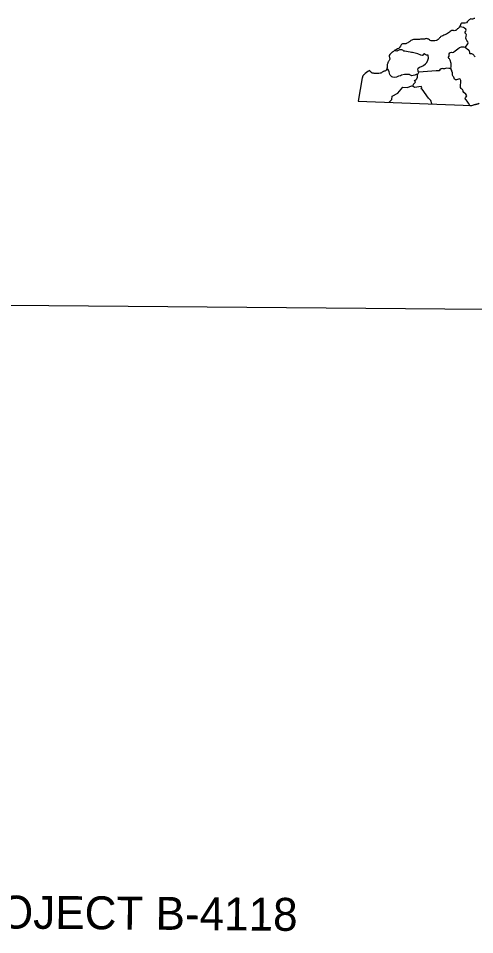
# Model space of a CAD drawing. Extents: x 1379453 to 1387082, y 594364 to 596664.
# Drawn here: x 1382008 to 1382285, y 595562 to 596118 of the extents above; entities that cross this region are included whole.
import ezdxf

# ---------------------------------------------------------------- set-up
doc = ezdxf.new("R2010")
doc.units = 0
for name, color, linetype in [('Old_Level_32', 7, 'Continuous'), ('Pattern 8', 7, 'Continuous'), ('Prop Horizontal Alignment Station Label', 7, 'Continuous')]:
    doc.layers.add(name, color=color, linetype=linetype)

msp = doc.modelspace()

# ---------------------------------------------------------------- linework, layer by layer
at = {"layer": 'Old_Level_32'}
msp.add_lwpolyline([(1380751.9, 595954.74), (1382700.35, 595938.42), (1382692.2, 594965.67), (1380743.75, 594981.99)], close=True, dxfattribs=at)
at = {"layer": 'Pattern 8'}
for points in [[(1382285.45, 596118.46), (1382285.01, 596118.31), (1382284.64, 596118.19), (1382284.2, 596118.04), (1382283.73, 596118.05), (1382283.14, 596118.12), (1382282.79, 596118.03), (1382282.54, 596117.81), (1382282.13, 596117.57), (1382281.69, 596117.1), (1382281.31, 596116.67), (1382280.96, 596116.27), (1382280.39, 596115.81), (1382279.73, 596115.6), (1382279.04, 596115.54), (1382278.2, 596115.58), (1382277.57, 596115.47), (1382277.13, 596115.22), (1382277, 596114.94), (1382276.81, 596114.66)], [(1382285.45, 596118.46), (1382285.01, 596118.31), (1382284.64, 596118.19), (1382284.2, 596118.04), (1382283.73, 596118.05), (1382283.14, 596118.12), (1382282.79, 596118.03), (1382282.54, 596117.81), (1382282.13, 596117.57), (1382281.69, 596117.1), (1382281.31, 596116.67), (1382280.96, 596116.27), (1382280.39, 596115.81), (1382279.73, 596115.6), (1382279.04, 596115.54), (1382278.2, 596115.58), (1382277.57, 596115.47), (1382277.13, 596115.22), (1382277, 596114.94), (1382276.81, 596114.66)], [(1382276.2, 596113.39), (1382276.11, 596113.11), (1382275.98, 596112.86), (1382275.66, 596112.55), (1382275.38, 596112.37), (1382274.91, 596112), (1382274.72, 596111.88), (1382274.56, 596111.69), (1382274.34, 596111.44), (1382274.15, 596111.26), (1382273.93, 596111.1), (1382273.64, 596110.98), (1382273.02, 596110.93), (1382272.68, 596111.06), (1382272.36, 596111.15), (1382272.02, 596111.16), (1382271.77, 596111.13), (1382271.46, 596111.01), (1382271.17, 596110.86), (1382270.51, 596110.4), (1382270.1, 596110.12), (1382269.6, 596109.66), (1382269.19, 596109.38), (1382268.93, 596109.2), (1382268.37, 596108.89), (1382267.8, 596108.62), (1382267.27, 596108.34), (1382266.73, 596108.19), (1382266.01, 596107.92), (1382265.42, 596107.71), (1382264.91, 596107.46), (1382264.72, 596107.19), (1382264.53, 596106.88), (1382264.15, 596106.6), (1382263.83, 596106.26), (1382263.2, 596105.58), (1382262.63, 596105.18), (1382262.16, 596105), (1382261.22, 596104.79), (1382260.44, 596104.74), (1382259.75, 596104.75), (1382259.1, 596104.85), (1382258.45, 596105.07), (1382257.95, 596105.36), (1382257.42, 596105.71), (1382257.11, 596105.9), (1382256.77, 596106.06), (1382256.24, 596106.13), (1382255.83, 596106.11), (1382255.39, 596105.96), (1382255.05, 596105.8), (1382254.45, 596105.75), (1382254.11, 596105.81), (1382253.64, 596105.85), (1382253.17, 596105.83), (1382253.02, 596105.83), (1382252.99, 596105.83)], [(1382276.2, 596113.39), (1382276.11, 596113.11), (1382275.98, 596112.86), (1382275.66, 596112.55), (1382275.38, 596112.37), (1382274.91, 596112), (1382274.72, 596111.88), (1382274.56, 596111.69), (1382274.34, 596111.44), (1382274.15, 596111.26), (1382273.93, 596111.1), (1382273.64, 596110.98), (1382273.02, 596110.93), (1382272.68, 596111.06), (1382272.36, 596111.15), (1382272.02, 596111.16), (1382271.77, 596111.13), (1382271.46, 596111.01), (1382271.17, 596110.86), (1382270.51, 596110.4), (1382270.1, 596110.12), (1382269.6, 596109.66), (1382269.19, 596109.38), (1382268.93, 596109.2), (1382268.37, 596108.89), (1382267.8, 596108.62), (1382267.27, 596108.34), (1382266.73, 596108.19), (1382266.01, 596107.92), (1382265.42, 596107.71), (1382264.91, 596107.46), (1382264.72, 596107.19), (1382264.53, 596106.88), (1382264.15, 596106.6), (1382263.83, 596106.26), (1382263.2, 596105.58), (1382262.63, 596105.18), (1382262.16, 596105), (1382261.22, 596104.79), (1382260.44, 596104.74), (1382259.75, 596104.75), (1382259.1, 596104.85), (1382258.45, 596105.07), (1382257.95, 596105.36), (1382257.42, 596105.71), (1382257.11, 596105.9), (1382256.77, 596106.06), (1382256.24, 596106.13), (1382255.83, 596106.11), (1382255.39, 596105.96), (1382255.05, 596105.8), (1382254.45, 596105.75), (1382254.11, 596105.81), (1382253.64, 596105.85), (1382253.17, 596105.83), (1382253.02, 596105.83), (1382252.99, 596105.83)], [(1382276.81, 596114.66), (1382276.78, 596114.41), (1382276.68, 596114.2), (1382276.56, 596114.04), (1382276.55, 596113.85), (1382276.43, 596113.64), (1382276.33, 596113.51), (1382276.2, 596113.39)], [(1382276.81, 596114.66), (1382276.78, 596114.41), (1382276.68, 596114.2), (1382276.56, 596114.04), (1382276.55, 596113.85), (1382276.43, 596113.64), (1382276.33, 596113.51), (1382276.2, 596113.39)], [(1382279.93, 596100.91), (1382281.23, 596102.95), (1382281.4, 596103.54), (1382281.19, 596104.2), (1382280.6, 596105.02), (1382280.2, 596105.75), (1382280.15, 596106.4), (1382280.32, 596107.59), (1382280.46, 596108.52), (1382280.37, 596108.78), (1382279.9, 596109.19), (1382279.56, 596109.57), (1382279.7, 596110.1), (1382280.02, 596110.69), (1382280.24, 596111.28), (1382280, 596111.94), (1382279.32, 596112.51), (1382278.6, 596112.89), (1382277.7, 596113), (1382276.73, 596113.23), (1382276.2, 596113.39)], [(1382279.93, 596100.91), (1382281.23, 596102.95), (1382281.4, 596103.54), (1382281.19, 596104.2), (1382280.6, 596105.02), (1382280.2, 596105.75), (1382280.15, 596106.4), (1382280.32, 596107.59), (1382280.46, 596108.52), (1382280.37, 596108.78), (1382279.9, 596109.19), (1382279.56, 596109.57), (1382279.7, 596110.1), (1382280.02, 596110.69), (1382280.24, 596111.28), (1382280, 596111.94), (1382279.32, 596112.51), (1382278.6, 596112.89), (1382277.7, 596113), (1382276.73, 596113.23), (1382276.2, 596113.39)], [(1382252.99, 596105.83), (1382252.64, 596105.74), (1382251.95, 596105.68), (1382251.33, 596105.63), (1382250.42, 596105.61), (1382249.8, 596105.68), (1382249.01, 596105.66), (1382248.26, 596105.57), (1382247.73, 596105.46), (1382247.23, 596105.27), (1382246.76, 596105), (1382246.41, 596104.72), (1382246.06, 596104.44), (1382245.75, 596104.14), (1382245.4, 596103.92), (1382245.08, 596103.71), (1382244.77, 596103.52), (1382244.27, 596103.31), (1382244.11, 596103.12), (1382243.67, 596103.07), (1382243.29, 596103.04), (1382242.92, 596103.05), (1382242.45, 596102.99), (1382241.98, 596102.96), (1382241.7, 596102.9), (1382241.26, 596102.69), (1382241.01, 596102.47), (1382240.82, 596102.29), (1382240.66, 596102.01), (1382240.37, 596101.54), (1382239.99, 596100.86), (1382239.73, 596100.71), (1382239.54, 596100.43), (1382239.26, 596100.21), (1382239.1, 596100.09), (1382238.6, 596099.85), (1382237.94, 596099.57), (1382237.53, 596099.33), (1382237.25, 596099.18), (1382237, 596099.12)], [(1382252.99, 596105.83), (1382252.64, 596105.74), (1382251.95, 596105.68), (1382251.33, 596105.63), (1382250.42, 596105.61), (1382249.8, 596105.68), (1382249.01, 596105.66), (1382248.26, 596105.57), (1382247.73, 596105.46), (1382247.23, 596105.27), (1382246.76, 596105), (1382246.41, 596104.72), (1382246.06, 596104.44), (1382245.75, 596104.14), (1382245.4, 596103.92), (1382245.08, 596103.71), (1382244.77, 596103.52), (1382244.27, 596103.31), (1382244.11, 596103.12), (1382243.67, 596103.07), (1382243.29, 596103.04), (1382242.92, 596103.05), (1382242.45, 596102.99), (1382241.98, 596102.96), (1382241.7, 596102.9), (1382241.26, 596102.69), (1382241.01, 596102.47), (1382240.82, 596102.29), (1382240.66, 596102.01), (1382240.37, 596101.54), (1382239.99, 596100.86), (1382239.73, 596100.71), (1382239.54, 596100.43), (1382239.26, 596100.21), (1382239.1, 596100.09), (1382238.6, 596099.85), (1382237.94, 596099.57), (1382237.53, 596099.33), (1382237.25, 596099.18), (1382237, 596099.12)], [(1382237, 596099.12), (1382236.81, 596098.87), (1382236.52, 596098.62), (1382236.05, 596098.28), (1382235.83, 596098.19), (1382235.51, 596097.98), (1382235.26, 596097.92), (1382235.04, 596097.61), (1382234.47, 596097.05), (1382234.4, 596096.8), (1382233.99, 596096.4), (1382233.83, 596096.16), (1382233.61, 596096), (1382233.42, 596095.41), (1382233.66, 596094.53), (1382233.84, 596094), (1382233.83, 596093.59), (1382233.74, 596093.22), (1382233.58, 596092.91), (1382233.32, 596092.63), (1382233.07, 596092.23), (1382232.91, 596091.98), (1382232.78, 596091.48), (1382232.65, 596091.2), (1382232.58, 596090.89), (1382232.39, 596090.39), (1382232.35, 596090.11), (1382232.26, 596089.74), (1382232.27, 596088.71), (1382232.24, 596088.42), (1382232.17, 596088.14)], [(1382237, 596099.12), (1382236.81, 596098.87), (1382236.52, 596098.62), (1382236.05, 596098.28), (1382235.83, 596098.19), (1382235.51, 596097.98), (1382235.26, 596097.92), (1382235.04, 596097.61), (1382234.47, 596097.05), (1382234.4, 596096.8), (1382233.99, 596096.4), (1382233.83, 596096.16), (1382233.61, 596096), (1382233.42, 596095.41), (1382233.66, 596094.53), (1382233.84, 596094), (1382233.83, 596093.59), (1382233.74, 596093.22), (1382233.58, 596092.91), (1382233.32, 596092.63), (1382233.07, 596092.23), (1382232.91, 596091.98), (1382232.78, 596091.48), (1382232.65, 596091.2), (1382232.58, 596090.89), (1382232.39, 596090.39), (1382232.35, 596090.11), (1382232.26, 596089.74), (1382232.27, 596088.71), (1382232.24, 596088.42), (1382232.17, 596088.14)], [(1382257.24, 596096.15), (1382256.21, 596096.19), (1382255.34, 596096.55), (1382254.75, 596096.9), (1382254.41, 596096.72), (1382254.02, 596096.19), (1382253.52, 596095.88), (1382252.8, 596096.08), (1382250.84, 596096.89), (1382249.32, 596097.28), (1382248.54, 596097.54), (1382247.67, 596097.71), (1382247.04, 596097.68), (1382246.29, 596097.85), (1382244.98, 596098.11), (1382244.14, 596098.31), (1382243.05, 596098.54), (1382242.49, 596098.46), (1382242.12, 596098.62), (1382241.81, 596099.06), (1382241.16, 596099.35), (1382240.28, 596099.39), (1382239.69, 596099.27), (1382238.96, 596098.87), (1382238.33, 596098.6), (1382237.74, 596098.73), (1382237.43, 596098.8), (1382237, 596099.12)], [(1382257.24, 596096.15), (1382256.21, 596096.19), (1382255.34, 596096.55), (1382254.75, 596096.9), (1382254.41, 596096.72), (1382254.02, 596096.19), (1382253.52, 596095.88), (1382252.8, 596096.08), (1382250.84, 596096.89), (1382249.32, 596097.28), (1382248.54, 596097.54), (1382247.67, 596097.71), (1382247.04, 596097.68), (1382246.29, 596097.85), (1382244.98, 596098.11), (1382244.14, 596098.31), (1382243.05, 596098.54), (1382242.49, 596098.46), (1382242.12, 596098.62), (1382241.81, 596099.06), (1382241.16, 596099.35), (1382240.28, 596099.39), (1382239.69, 596099.27), (1382238.96, 596098.87), (1382238.33, 596098.6), (1382237.74, 596098.73), (1382237.43, 596098.8), (1382237, 596099.12)], [(1382251.58, 596085.72), (1382251.18, 596086.22), (1382251.03, 596086.82), (1382250.92, 596087.67), (1382251.15, 596088.22), (1382252, 596088.87), (1382253.19, 596089.26), (1382254.29, 596089.84), (1382255.58, 596090.73), (1382256.34, 596091.69), (1382257.08, 596093.06), (1382257.5, 596094.3), (1382257.24, 596096.15)], [(1382251.58, 596085.72), (1382251.18, 596086.22), (1382251.03, 596086.82), (1382250.92, 596087.67), (1382251.15, 596088.22), (1382252, 596088.87), (1382253.19, 596089.26), (1382254.29, 596089.84), (1382255.58, 596090.73), (1382256.34, 596091.69), (1382257.08, 596093.06), (1382257.5, 596094.3), (1382257.24, 596096.15)], [(1382270.99, 596088.01), (1382271.19, 596089.17), (1382271.24, 596091.07), (1382270.58, 596093.05), (1382270.15, 596093.84), (1382269.69, 596094.09), (1382269.47, 596094.56), (1382269.6, 596094.91), (1382269.95, 596095.43), (1382269.99, 596096.15), (1382269.97, 596097), (1382270.26, 596097.46), (1382270.76, 596097.77), (1382271.39, 596097.82), (1382272.11, 596097.75), (1382272.67, 596097.87), (1382273.65, 596098.73), (1382275.17, 596099.96), (1382276.27, 596100.7), (1382277.43, 596101.09), (1382278.84, 596101.11), (1382279.55, 596101.04), (1382279.93, 596100.91)], [(1382270.99, 596088.01), (1382271.19, 596089.17), (1382271.24, 596091.07), (1382270.58, 596093.05), (1382270.15, 596093.84), (1382269.69, 596094.09), (1382269.47, 596094.56), (1382269.6, 596094.91), (1382269.95, 596095.43), (1382269.99, 596096.15), (1382269.97, 596097), (1382270.26, 596097.46), (1382270.76, 596097.77), (1382271.39, 596097.82), (1382272.11, 596097.75), (1382272.67, 596097.87), (1382273.65, 596098.73), (1382275.17, 596099.96), (1382276.27, 596100.7), (1382277.43, 596101.09), (1382278.84, 596101.11), (1382279.55, 596101.04), (1382279.93, 596100.91)], [(1382285.67, 596095.12), (1382285.21, 596095.68), (1382284.9, 596096.13), (1382284.5, 596096.51), (1382283.75, 596096.83), (1382283.19, 596096.83), (1382282.69, 596096.93), (1382282.51, 596097.19), (1382282.45, 596097.81), (1382282.24, 596098.31), (1382282, 596098.88), (1382281.66, 596099.2), (1382280.94, 596099.71), (1382280.51, 596100.15), (1382280.36, 596100.37), (1382279.93, 596100.91)], [(1382285.67, 596095.12), (1382285.21, 596095.68), (1382284.9, 596096.13), (1382284.5, 596096.51), (1382283.75, 596096.83), (1382283.19, 596096.83), (1382282.69, 596096.93), (1382282.51, 596097.19), (1382282.45, 596097.81), (1382282.24, 596098.31), (1382282, 596098.88), (1382281.66, 596099.2), (1382280.94, 596099.71), (1382280.51, 596100.15), (1382280.36, 596100.37), (1382279.93, 596100.91)], [(1382232.17, 596088.14), (1382232.07, 596087.55), (1382231.66, 596087.03), (1382231.44, 596086.81), (1382231.19, 596086.66), (1382230.87, 596086.47), (1382230.62, 596086.38), (1382230.37, 596086.38), (1382230.12, 596086.26), (1382229.71, 596085.99), (1382229.36, 596085.71), (1382229.11, 596085.56), (1382228.83, 596085.37), (1382228.48, 596085.19), (1382228.07, 596085.13), (1382227.14, 596085.05), (1382226.45, 596084.96), (1382225.63, 596084.94), (1382224.92, 596084.98), (1382224.48, 596085.02), (1382223.95, 596085.06), (1382223.73, 596085.06), (1382223.36, 596085.16), (1382223.11, 596085.25), (1382222.89, 596085.38), (1382222.7, 596085.57), (1382222.52, 596085.7), (1382222.24, 596085.95), (1382222.12, 596086.17), (1382222, 596086.46), (1382221.87, 596086.58), (1382221.72, 596086.65), (1382221.5, 596086.68), (1382221.25, 596086.62), (1382220.93, 596086.44), (1382220.55, 596086.13), (1382218.91, 596084.87), (1382218.44, 596084.5), (1382218.03, 596084.16), (1382217.81, 596083.91), (1382217.65, 596083.66), (1382217.52, 596083.45), (1382217.43, 596083.29), (1382217.39, 596083.11), (1382217.29, 596082.76), (1382217.23, 596082.61), (1382217.1, 596082.36)], [(1382232.17, 596088.14), (1382232.07, 596087.55), (1382231.66, 596087.03), (1382231.44, 596086.81), (1382231.19, 596086.66), (1382230.87, 596086.47), (1382230.62, 596086.38), (1382230.37, 596086.38), (1382230.12, 596086.26), (1382229.71, 596085.99), (1382229.36, 596085.71), (1382229.11, 596085.56), (1382228.83, 596085.37), (1382228.48, 596085.19), (1382228.07, 596085.13), (1382227.14, 596085.05), (1382226.45, 596084.96), (1382225.63, 596084.94), (1382224.92, 596084.98), (1382224.48, 596085.02), (1382223.95, 596085.06), (1382223.73, 596085.06), (1382223.36, 596085.16), (1382223.11, 596085.25), (1382222.89, 596085.38), (1382222.7, 596085.57), (1382222.52, 596085.7), (1382222.24, 596085.95), (1382222.12, 596086.17), (1382222, 596086.46), (1382221.87, 596086.58), (1382221.72, 596086.65), (1382221.5, 596086.68), (1382221.25, 596086.62), (1382220.93, 596086.44), (1382220.55, 596086.13), (1382218.91, 596084.87), (1382218.44, 596084.5), (1382218.03, 596084.16), (1382217.81, 596083.91), (1382217.65, 596083.66), (1382217.52, 596083.45), (1382217.43, 596083.29), (1382217.39, 596083.11), (1382217.29, 596082.76), (1382217.23, 596082.61), (1382217.1, 596082.36)], [(1382250.6, 596084.29), (1382249.88, 596084.27), (1382249.03, 596083.88), (1382248.15, 596083.67), (1382247.34, 596083.52), (1382246.9, 596083.71), (1382246.5, 596083.88), (1382246.03, 596084.19), (1382245.88, 596084.29), (1382245.25, 596084.42), (1382244.41, 596084.37), (1382243.72, 596084.35), (1382243.22, 596084.41), (1382242.75, 596084.42), (1382241.06, 596083.88), (1382240.43, 596083.48), (1382239.11, 596083.25), (1382237.95, 596082.76), (1382236.7, 596082.56), (1382235.76, 596082.63), (1382235.14, 596083.01), (1382234.77, 596083.24), (1382234.09, 596083.9), (1382233.94, 596084.4), (1382233.55, 596085.97), (1382233.06, 596086.88), (1382232.67, 596087.67), (1382232.17, 596088.14)], [(1382250.6, 596084.29), (1382249.88, 596084.27), (1382249.03, 596083.88), (1382248.15, 596083.67), (1382247.34, 596083.52), (1382246.9, 596083.71), (1382246.5, 596083.88), (1382246.03, 596084.19), (1382245.88, 596084.29), (1382245.25, 596084.42), (1382244.41, 596084.37), (1382243.72, 596084.35), (1382243.22, 596084.41), (1382242.75, 596084.42), (1382241.06, 596083.88), (1382240.43, 596083.48), (1382239.11, 596083.25), (1382237.95, 596082.76), (1382236.7, 596082.56), (1382235.76, 596082.63), (1382235.14, 596083.01), (1382234.77, 596083.24), (1382234.09, 596083.9), (1382233.94, 596084.4), (1382233.55, 596085.97), (1382233.06, 596086.88), (1382232.67, 596087.67), (1382232.17, 596088.14)], [(1382250.6, 596084.29), (1382250.85, 596084.63), (1382251.14, 596085.01), (1382251.36, 596085.28), (1382251.58, 596085.72)], [(1382250.6, 596084.29), (1382250.85, 596084.63), (1382251.14, 596085.01), (1382251.36, 596085.28), (1382251.58, 596085.72)], [(1382270.99, 596088.01), (1382269.67, 596088), (1382268.27, 596088.17), (1382267.2, 596087.84), (1382266.33, 596087.79), (1382265.83, 596087.98), (1382265.02, 596087.74), (1382264.29, 596087.22), (1382263.97, 596086.66), (1382263.06, 596086.49), (1382262.06, 596086.65), (1382251.58, 596085.72)], [(1382270.99, 596088.01), (1382269.67, 596088), (1382268.27, 596088.17), (1382267.2, 596087.84), (1382266.33, 596087.79), (1382265.83, 596087.98), (1382265.02, 596087.74), (1382264.29, 596087.22), (1382263.97, 596086.66), (1382263.06, 596086.49), (1382262.06, 596086.65), (1382251.58, 596085.72)], [(1382282.49, 596065.5), (1382281.67, 596066.94), (1382280.81, 596068.14), (1382280.19, 596068.87), (1382279.85, 596069.25), (1382279.61, 596069.69), (1382279.8, 596070.19), (1382280.31, 596070.74), (1382280.6, 596071.3), (1382280.45, 596071.87), (1382280.08, 596072.34), (1382278.9, 596073.32), (1382278.53, 596073.92), (1382278.42, 596074.45), (1382278.08, 596075.27), (1382277.59, 596075.53), (1382277.15, 596075.94), (1382276.91, 596076.38), (1382276.79, 596076.69), (1382276.96, 596080.72), (1382276.87, 596081.07), (1382276.57, 596081.54), (1382276.19, 596081.67), (1382275.6, 596081.58), (1382275, 596081.28), (1382274.44, 596081.13), (1382273.78, 596081.2), (1382273.28, 596081.52), (1382273.04, 596082.08), (1382272.77, 596082.68), (1382272.37, 596083.22), (1382271.97, 596083.88), (1382271.98, 596084.44), (1382271.92, 596085.31), (1382271.65, 596086.32), (1382271.5, 596086.82), (1382271.23, 596087.45), (1382271.11, 596087.89), (1382270.99, 596088.01)], [(1382282.49, 596065.5), (1382281.67, 596066.94), (1382280.81, 596068.14), (1382280.19, 596068.87), (1382279.85, 596069.25), (1382279.61, 596069.69), (1382279.8, 596070.19), (1382280.31, 596070.74), (1382280.6, 596071.3), (1382280.45, 596071.87), (1382280.08, 596072.34), (1382278.9, 596073.32), (1382278.53, 596073.92), (1382278.42, 596074.45), (1382278.08, 596075.27), (1382277.59, 596075.53), (1382277.15, 596075.94), (1382276.91, 596076.38), (1382276.79, 596076.69), (1382276.96, 596080.72), (1382276.87, 596081.07), (1382276.57, 596081.54), (1382276.19, 596081.67), (1382275.6, 596081.58), (1382275, 596081.28), (1382274.44, 596081.13), (1382273.78, 596081.2), (1382273.28, 596081.52), (1382273.04, 596082.08), (1382272.77, 596082.68), (1382272.37, 596083.22), (1382271.97, 596083.88), (1382271.98, 596084.44), (1382271.92, 596085.31), (1382271.65, 596086.32), (1382271.5, 596086.82), (1382271.23, 596087.45), (1382271.11, 596087.89), (1382270.99, 596088.01)], [(1382217.1, 596082.36), (1382214.62, 596068.18), (1382283.68, 596065.58)], [(1382217.1, 596082.36), (1382214.62, 596068.18), (1382283.68, 596065.58)], [(1382247.79, 596077.2), (1382248.04, 596077.45), (1382248.37, 596078.41), (1382248.72, 596078.85), (1382249.1, 596079.19), (1382249.38, 596079.53), (1382249.42, 596079.93), (1382249.33, 596080.03), (1382249.08, 596080.31), (1382248.93, 596080.69)], [(1382247.79, 596077.2), (1382248.04, 596077.45), (1382248.37, 596078.41), (1382248.72, 596078.85), (1382249.1, 596079.19), (1382249.38, 596079.53), (1382249.42, 596079.93), (1382249.33, 596080.03), (1382249.08, 596080.31), (1382248.93, 596080.69)], [(1382248.93, 596080.69), (1382249.24, 596081), (1382249.97, 596081.24), (1382250.41, 596081.8), (1382250.73, 596082.7), (1382250.77, 596083.39), (1382250.72, 596083.79), (1382250.6, 596084.29)], [(1382248.93, 596080.69), (1382249.24, 596081), (1382249.97, 596081.24), (1382250.41, 596081.8), (1382250.73, 596082.7), (1382250.77, 596083.39), (1382250.72, 596083.79), (1382250.6, 596084.29)], [(1382233.42, 596067.45), (1382235.23, 596069.21), (1382235.35, 596071.25), (1382238.74, 596073.06), (1382241.84, 596076.57), (1382244.62, 596076.38), (1382247.03, 596077.44), (1382247.79, 596077.2)], [(1382233.42, 596067.45), (1382235.23, 596069.21), (1382235.35, 596071.25), (1382238.74, 596073.06), (1382241.84, 596076.57), (1382244.62, 596076.38), (1382247.03, 596077.44), (1382247.79, 596077.2)], [(1382259.33, 596066.45), (1382258.88, 596068.65), (1382257.48, 596069.97), (1382253.49, 596075.45), (1382253.02, 596075.66), (1382253.45, 596076.5), (1382252.93, 596076.97), (1382248.94, 596076.54), (1382247.79, 596077.2)], [(1382259.33, 596066.45), (1382258.88, 596068.65), (1382257.48, 596069.97), (1382253.49, 596075.45), (1382253.02, 596075.66), (1382253.45, 596076.5), (1382252.93, 596076.97), (1382248.94, 596076.54), (1382247.79, 596077.2)], [(1382282.49, 596065.5), (1382282.78, 596065.52), (1382283.28, 596065.52), (1382283.68, 596065.58), (1382284.37, 596065.76), (1382284.72, 596065.88), (1382285.03, 596065.97), (1382285.31, 596066.09), (1382285.85, 596066.21), (1382286.07, 596066.27), (1382286.54, 596066.35), (1382286.85, 596066.41), (1382286.94, 596066.44), (1382287.19, 596066.5), (1382287.48, 596066.56), (1382287.76, 596066.65), (1382288.04, 596066.77), (1382288.07, 596066.9)], [(1382282.49, 596065.5), (1382282.78, 596065.52), (1382283.28, 596065.52), (1382283.68, 596065.58), (1382284.37, 596065.76), (1382284.72, 596065.88), (1382285.03, 596065.97), (1382285.31, 596066.09), (1382285.85, 596066.21), (1382286.07, 596066.27), (1382286.54, 596066.35), (1382286.85, 596066.41), (1382286.94, 596066.44), (1382287.19, 596066.5), (1382287.48, 596066.56), (1382287.76, 596066.65), (1382288.04, 596066.77), (1382288.07, 596066.9)]]:
    msp.add_lwpolyline(points, dxfattribs=at)

# ---------------------------------------------------------------- texts
at = {"layer": 'Prop Horizontal Alignment Station Label'}
msp.add_text('END TIP PROJECT B-4118', height=20, rotation=359.52, dxfattribs=at).set_placement((1381846.41, 595566.95))

doc.saveas('drawing.dxf')
